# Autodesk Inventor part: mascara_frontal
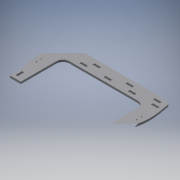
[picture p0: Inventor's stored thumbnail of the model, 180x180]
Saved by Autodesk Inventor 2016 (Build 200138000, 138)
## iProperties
Created: 2017-06
Part Number: mascara_frontal
Material: Generic
Document SubType Name: Modeling
Designer: laboratorioesan
Density: 1 g/cm^3
Appearance: Default
Author: laboratorioesan
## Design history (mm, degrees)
sketch "Sketch1"
  geometry: L1 (280, 0)-(340, 0) reference; L2 (340, 0)-(340, 18.5) reference; L3 (280, 18.5)-(340, 18.5) reference; L4 (280, 0)-(280, 18.5) reference; L5 (70, 0)-(130, 0) reference; L6 (130, 0)-(130, 18.5) reference; L7 (70, 18.5)-(130, 18.5) reference; L8 (70, 0)-(70, 18.5) reference; L9 (500, 0)-(560, 0) reference; L10 (560, 0)-(560, 18.5) reference; L11 (500, 18.5)-(560, 18.5) reference; L12 (500, 0)-(500, 18.5) reference; L13 (720, 0)-(780, 0) reference; L14 (780, 0)-(780, 18.5) reference; L15 (720, 18.5)-(780, 18.5) reference; L16 (720, 0)-(720, 18.5) reference; L17 (930, 0)-(990, 0) reference; L18 (990, 0)-(990, 18.5) reference; L19 (930, 18.5)-(990, 18.5) reference; L20 (930, 0)-(930, 18.5) reference; L21 (0, 0)-(0, 18.5) reference; L22 (130, -432.5)-(130, 0) reference; L23 (111.5, -432.5)-(111.5, 0) reference; L24 (930, -432.5)-(930, 0) reference; L25 (948.5, -432.5)-(948.5, 0) reference; L26 (1060, 0)-(1060, 18.5) reference; L27 (990, 104.496)-(70, 104.496); L28 (70, 104.496)-(0, 0); L29 (0, 0)-(0, -84.685); L30 (57, -270.723)-(130, -270.723); L31 (1060, 0)-(990, 104.496); L32 (130, -270.723)-(160, -270.723); L33 (160, -270.723)-(160, -30); L34 (160, -30)-(900, -30); L35 (900, -30)-(900, -270.723); L36 (900, -270.723)-(1003, -270.723); L37 (1003, -270.723)-(1060, -84.685); L38 (1060, -84.685)-(1060, 0); L39 (0, -84.685)-(57, -270.723)
  constraints: 26 end point, 4 perpendicular, 3 point on line, 2 horizontal, 2 horizontal alignment, 2 vertical, 2 vertical alignment
  dimensions: "d0" = 30 distance of L30.end L32.end; "d1" = 30 distance between parallel lines of L24 L35; "d2" = 30 horizontal distance of L17.start L34.end; "d3" = 70 distance between parallel lines of L29 L8; "d4" = 70 distance between parallel lines of L38 L18 (derived); "d6" = 103 distance of L35.end L36.end; "d7" = 103 distance of L30.start L32.end
extrude "Extrusion1" new body sketch "Sketch1" distance "d8" = 18.5; taper "d9" = 0 deg
fillet "Fillet1" dims "d10" = 60
fillet "Fillet2" dims "d11" = 60
sketch "Sketch2"
  geometry: L1 (930, 0)-(930, 18.5) reference; L2 (930, 18.5)-(990, 18.5) reference; L3 (990, 18.5)-(990, 0) reference; L4 (990, 0)-(930, 0) reference; L5 (720, 0)-(720, 18.5) reference; L6 (720, 18.5)-(780, 18.5) reference; L7 (780, 18.5)-(780, 0) reference; L8 (780, 0)-(720, 0) reference; L9 (500, 0)-(500, 18.5) reference; L10 (500, 18.5)-(560, 18.5) reference; L11 (560, 18.5)-(560, 0) reference; L12 (560, 0)-(500, 0) reference; L13 (70, 0)-(70, 18.5) reference; L14 (70, 18.5)-(130, 18.5) reference; L15 (130, 18.5)-(130, 0) reference; L16 (130, 0)-(70, 0) reference; L17 (280, 0)-(280, 18.5) reference; L18 (280, 18.5)-(340, 18.5) reference; L19 (340, 18.5)-(340, 0) reference; L20 (340, 0)-(280, 0) reference; L21 (52.176, 77.889)-(0, 0) reference; L22 (0, 0)-(0, -84.685) reference; L23 (0, -84.685)-(44.002, -228.3) reference; L24 (101.37, -270.723)-(160, -270.723) reference; L25 (160, -270.723)-(160, -90) reference; L26 (220, -30)-(840, -30) reference; L27 (900, -90)-(900, -270.723) reference; L28 (900, -270.723)-(958.63, -270.723) reference; L29 (1015.998, -228.3)-(1060, -84.685) reference; L30 (1060, -84.685)-(1060, 0) reference; L31 (1060, 0)-(1007.824, 77.889) reference; L32 (957.975, 104.496)-(102.025, 104.496) reference; L33 (960, 67)-(900, 67); L34 (900, 67)-(900, 48.5); L35 (900, 48.5)-(960, 48.5); L36 (960, 48.5)-(960, 67); L37 (710, 48.5)-(650, 48.5); L38 (650, 48.5)-(650, 67); L39 (650, 67)-(710, 67); L40 (710, 67)-(710, 48.5); L41 (410, 48.5)-(350, 48.5); L42 (350, 48.5)-(350, 67); L43 (350, 67)-(410, 67); L44 (410, 67)-(410, 48.5); L45 (160, 48.5)-(100, 48.5); L46 (100, 48.5)-(100, 67); L47 (100, 67)-(160, 67); L48 (160, 67)-(160, 48.5); L49 (948.5, -432.5)-(948.5, 0) reference; L50 (997, -100)-(978.5, -100); L51 (978.5, -100)-(978.5, -40); L52 (978.5, -40)-(997, -40); L53 (997, -40)-(997, -100); L54 (997, -155)-(978.5, -155); L55 (978.5, -155)-(978.5, -215); L56 (978.5, -215)-(997, -215); L57 (997, -215)-(997, -155); L58 (111.5, -432.5)-(111.5, 0) reference; L59 (81.5, -100)-(63, -100); L60 (63, -100)-(63, -40); L61 (63, -40)-(81.5, -40); L62 (81.5, -40)-(81.5, -100); L63 (81.5, -155)-(63, -155); L64 (63, -155)-(63, -215)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; A1 r 60 centre (102.025, 44.496) between (102.025, 104.496) and (52.176, 77.889) reference; A2 r 60 centre (101.37, -210.723) between (44.002, -228.3) and (101.37, -270.723) reference; A3 r 60 centre (220, -90) between (220, -30) and (160, -90) reference; A4 r 60 centre (840, -90) between (900, -90) and (840, -30) reference; A5 r 60 centre (958.63, -210.723) between (958.63, -270.723) and (1015.998, -228.3) reference; A6 r 60 centre (957.975, 44.496) between (1007.824, 77.889) and (957.975, 104.496) reference; 6 further points
  constraints: 64 end point, 16 parallel, 8 horizontal, 8 perpendicular, 7 horizontal alignment, 5 midpoint, 5 point on line, 4 vertical alignment
  dimensions: "d12" = 60 distance of L35.end L34.end; "d13" = 18.5 distance of L34.end L33.end; "d14" = 60 distance of L38.end L39.end; "d15" = 60 distance of L42.end L43.end; "d16" = 60 distance of L46.end L47.end; "d17" = 30 distance from line of L1.end L35; "d18" = 190 distance of L47.end L42.end; "d19" = 190 distance of L37.start L34.end; "d20" = 18.5 distance of L51.end L52.end; "d21" = 60 distance of L50.end L51.end; "d22" = 40 vertical distance of L3.end L52.end; "d23" = 60 distance of L55.end L54.end; "d24" = 30 distance between parallel lines of L49 L51; "d25" = 18.5 distance of L60.end L61.end; "d26" = 60 distance of L64.end L63.end; "d27" = 55 distance of L50.end L54.end; "d28" = 30 distance from line of L58 L59.start
extrude "Extrusion2" cut sketch "Sketch2" distance "d29" = 18.5; taper "d30" = 0 deg
sketch "Sketch3"
  geometry: L1 (81.5, -40)-(81.5, -100) reference; L2 (81.5, -100)-(63, -100) reference; L3 (63, -100)-(63, -40) reference; L4 (63, -40)-(81.5, -40) reference; L5 (997, -40)-(997, -100) reference; L6 (997, -100)-(978.5, -100) reference; L7 (978.5, -100)-(978.5, -40) reference; L8 (978.5, -40)-(997, -40) reference; L9 (410, 67)-(410, 48.5) reference; L10 (410, 48.5)-(350, 48.5) reference; L11 (350, 48.5)-(350, 67) reference; L12 (350, 67)-(410, 67) reference; L13 (900, 48.5)-(900, 67) reference; L14 (900, 67)-(960, 67) reference; L15 (960, 67)-(960, 48.5) reference; L16 (960, 48.5)-(900, 48.5) reference; L17 (710, 67)-(710, 48.5) reference; L18 (710, 48.5)-(650, 48.5) reference; L19 (650, 48.5)-(650, 67) reference; L20 (650, 67)-(710, 67) reference; L21 (160, 67)-(160, 48.5) reference; L22 (160, 48.5)-(100, 48.5) reference; L23 (100, 48.5)-(100, 67) reference; L24 (100, 67)-(160, 67) reference; L25 (978.5, -215)-(978.5, -155) reference; L26 (978.5, -155)-(997, -155) reference; L27 (997, -155)-(997, -215) reference; L28 (997, -215)-(978.5, -215) reference; L29 (63, -215)-(63, -155) reference; L30 (63, -155)-(81.5, -155) reference; L31 (81.5, -155)-(81.5, -215) reference; L32 (81.5, -215)-(63, -215) reference; L33 (930, 0)-(930, 18.5) reference; L34 (930, 18.5)-(990, 18.5) reference; L35 (990, 18.5)-(990, 0) reference; L36 (990, 0)-(930, 0) reference; L37 (720, 0)-(720, 18.5) reference; L38 (720, 18.5)-(780, 18.5) reference; L39 (780, 18.5)-(780, 0) reference; L40 (780, 0)-(720, 0) reference; L41 (500, 0)-(500, 18.5) reference; L42 (500, 18.5)-(560, 18.5) reference; L43 (560, 18.5)-(560, 0) reference; L44 (560, 0)-(500, 0) reference; L45 (70, 0)-(70, 18.5) reference; L46 (70, 18.5)-(130, 18.5) reference; L47 (130, 18.5)-(130, 0) reference; L48 (130, 0)-(70, 0) reference; L49 (280, 0)-(280, 18.5) reference; L50 (280, 18.5)-(340, 18.5) reference; L51 (340, 18.5)-(340, 0) reference; L52 (340, 0)-(280, 0) reference; L53 (52.176, 77.889)-(0, 0) reference; L54 (0, 0)-(0, -84.685) reference; L55 (0, -84.685)-(44.002, -228.3) reference; L56 (101.37, -270.723)-(160, -270.723) reference; L57 (160, -270.723)-(160, -90) reference; L58 (220, -30)-(840, -30) reference; L59 (900, -90)-(900, -270.723) reference; L60 (900, -270.723)-(958.63, -270.723) reference; L61 (1015.998, -228.3)-(1060, -84.685) reference; L62 (1060, -84.685)-(1060, 0) reference; L63 (1060, 0)-(1007.824, 77.889) reference; L64 (957.975, 104.496)-(102.025, 104.496) reference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; A1 r 60 centre (102.025, 44.496) between (102.025, 104.496) and (52.176, 77.889) reference; A2 r 60 centre (101.37, -210.723) between (44.002, -228.3) and (101.37, -270.723) reference; A3 r 60 centre (220, -90) between (220, -30) and (160, -90) reference; A4 r 60 centre (840, -90) between (900, -90) and (840, -30) reference; A5 r 60 centre (958.63, -210.723) between (958.63, -270.723) and (1015.998, -228.3) reference; A6 r 60 centre (957.975, 44.496) between (1007.824, 77.889) and (957.975, 104.496) reference; 1 further point
  constraints: 16 end point, 4 parallel, 2 horizontal, 2 perpendicular
extrude "Extrusion3" join sketch "Sketch3" distance "d31" = 18.5; taper "d32" = 0 deg
sketch "Sketch4"
  geometry: L1 (410, 67)-(410, 48.5) reference; L2 (410, 48.5)-(350, 48.5) reference; L3 (350, 48.5)-(350, 67) reference; L4 (350, 67)-(410, 67) reference; L5 (900, 48.5)-(900, 67) reference; L6 (900, 67)-(960, 67) reference; L7 (960, 67)-(960, 48.5) reference; L8 (960, 48.5)-(900, 48.5) reference; L9 (710, 67)-(710, 48.5) reference; L10 (710, 48.5)-(650, 48.5) reference; L11 (650, 48.5)-(650, 67) reference; L12 (650, 67)-(710, 67) reference; L13 (160, 67)-(160, 48.5) reference; L14 (160, 48.5)-(100, 48.5) reference; L15 (100, 48.5)-(100, 67) reference; L16 (100, 67)-(160, 67) reference; L17 (978.5, -215)-(978.5, -155) reference; L18 (978.5, -155)-(997, -155) reference; L19 (997, -155)-(997, -215) reference; L20 (997, -215)-(978.5, -215) reference; L21 (63, -215)-(63, -155) reference; L22 (63, -155)-(81.5, -155) reference; L23 (81.5, -155)-(81.5, -215) reference; L24 (81.5, -215)-(63, -215) reference; L25 (930, 0)-(930, 18.5) reference; L26 (930, 18.5)-(990, 18.5) reference; L27 (990, 18.5)-(990, 0) reference; L28 (990, 0)-(930, 0) reference; L29 (720, 0)-(720, 18.5) reference; L30 (720, 18.5)-(780, 18.5) reference; L31 (780, 18.5)-(780, 0) reference; L32 (780, 0)-(720, 0) reference; L33 (500, 0)-(500, 18.5) reference; L34 (500, 18.5)-(560, 18.5) reference; L35 (560, 18.5)-(560, 0) reference; L36 (560, 0)-(500, 0) reference; L37 (70, 0)-(70, 18.5) reference; L38 (70, 18.5)-(130, 18.5) reference; L39 (130, 18.5)-(130, 0) reference; L40 (130, 0)-(70, 0) reference; L41 (280, 0)-(280, 18.5) reference; L42 (280, 18.5)-(340, 18.5) reference; L43 (340, 18.5)-(340, 0) reference; L44 (340, 0)-(280, 0) reference; L45 (52.176, 77.889)-(0, 0) reference; L46 (0, 0)-(0, -84.685) reference; L47 (0, -84.685)-(44.002, -228.3) reference; L48 (101.37, -270.723)-(160, -270.723) reference; L49 (160, -270.723)-(160, -90) reference; L50 (220, -30)-(840, -30) reference; L51 (900, -90)-(900, -270.723) reference; L52 (900, -270.723)-(958.63, -270.723) reference; L53 (1015.998, -228.3)-(1060, -84.685) reference; L54 (1060, -84.685)-(1060, 0) reference; L55 (1060, 0)-(1007.824, 77.889) reference; L56 (957.975, 104.496)-(102.025, 104.496) reference; L57 (530, -30)-(530, -112.619); L58 (130, -1020.137)-(130, -1080.137) reference; L59 (130, -1080.137)-(111.5, -1080.137) reference; L60 (111.5, -1080.137)-(111.5, -1020.137) reference; L61 (111.5, -1020.137)-(130, -1020.137) reference; L62 (111.5, -787.5)-(111.5, -769) reference; L63 (111.5, -769)-(150, -769) reference; L64 (150, -769)-(150, -412.5) reference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; C1 r 5.25 at (50, -140); C2 r 5.25 at (1010, -140); A1 r 60 centre (102.025, 44.496) between (102.025, 104.496) and (52.176, 77.889) reference; A2 r 60 centre (101.37, -210.723) between (44.002, -228.3) and (101.37, -270.723) reference; A3 r 60 centre (220, -90) between (220, -30) and (160, -90) reference; A4 r 60 centre (840, -90) between (900, -90) and (840, -30) reference; A5 r 60 centre (958.63, -210.723) between (958.63, -270.723) and (1015.998, -228.3) reference; A6 r 60 centre (957.975, 44.496) between (1007.824, 77.889) and (957.975, 104.496) reference; A7 r 3569.02 centre (-3531.655, -709.325) between (0, -1224.41) and (25, -412.5) reference; A8 r 60 centre (102.025, 44.496) between (102.025, 104.496) and (52.176, 77.889) reference; 1 further point
  constraints: 18 end point, 3 point on line, 2 centre point, 2 parallel, 2 vertical, 1 horizontal, 1 midpoint, 1 perpendicular, 1 symmetric about line, 1 other
  dimensions: "d33" = 10.5 diameter of C1; "d34" = 140 vertical distance of L37.start C1.centre; "d35" = 20 horizontal distance of L37.start C1.centre; "d38" = 18.5 distance of L99.end L98.end; "d39" = 60 distance of L98.end L97.end; "d40" = 15 distance between parallel lines of L77 L100
extrude "Extrusion4" cut sketch "Sketch4" distance "d36" = 18.5; taper "d37" = 0 deg
sketch "Sketch6"
  geometry: L1 (410, 67)-(410, 48.5) reference; L2 (410, 48.5)-(350, 48.5) reference; L3 (350, 48.5)-(350, 67) reference; L4 (350, 67)-(410, 67) reference; L5 (900, 48.5)-(900, 67) reference; L6 (900, 67)-(960, 67) reference; L7 (960, 67)-(960, 48.5) reference; L8 (960, 48.5)-(900, 48.5) reference; L9 (710, 67)-(710, 48.5) reference; L10 (710, 48.5)-(650, 48.5) reference; L11 (650, 48.5)-(650, 67) reference; L12 (650, 67)-(710, 67) reference; L13 (160, 67)-(160, 48.5) reference; L14 (160, 48.5)-(100, 48.5) reference; L15 (100, 48.5)-(100, 67) reference; L16 (100, 67)-(160, 67) reference; L17 (978.5, -215)-(978.5, -155) reference; L18 (978.5, -155)-(997, -155) reference; L19 (997, -155)-(997, -215) reference; L20 (997, -215)-(978.5, -215) reference; L21 (63, -215)-(63, -155) reference; L22 (63, -155)-(81.5, -155) reference; L23 (81.5, -155)-(81.5, -215) reference; L24 (81.5, -215)-(63, -215) reference; L25 (930, 0)-(930, 18.5) reference; L26 (930, 18.5)-(990, 18.5) reference; L27 (990, 18.5)-(990, 0) reference; L28 (990, 0)-(930, 0) reference; L29 (720, 0)-(720, 18.5) reference; L30 (720, 18.5)-(780, 18.5) reference; L31 (780, 18.5)-(780, 0) reference; L32 (780, 0)-(720, 0) reference; L33 (500, 0)-(500, 18.5) reference; L34 (500, 18.5)-(560, 18.5) reference; L35 (560, 18.5)-(560, 0) reference; L36 (560, 0)-(500, 0) reference; L37 (70, 0)-(70, 18.5) reference; L38 (70, 18.5)-(130, 18.5) reference; L39 (130, 18.5)-(130, 0) reference; L40 (130, 0)-(70, 0) reference; L41 (280, 0)-(280, 18.5) reference; L42 (280, 18.5)-(340, 18.5) reference; L43 (340, 18.5)-(340, 0) reference; L44 (340, 0)-(280, 0) reference; L45 (52.176, 77.889)-(0, 0) reference; L46 (0, 0)-(0, -84.685) reference; L47 (0, -84.685)-(44.002, -228.3) reference; L48 (101.37, -270.723)-(160, -270.723) reference; L49 (160, -270.723)-(160, -90) reference; L50 (220, -30)-(840, -30) reference; L51 (900, -90)-(900, -270.723) reference; L52 (900, -270.723)-(958.63, -270.723) reference; L53 (1015.998, -228.3)-(1060, -84.685) reference; L54 (1060, -84.685)-(1060, 0) reference; L55 (1060, 0)-(1007.824, 77.889) reference; L56 (957.975, 104.496)-(102.025, 104.496) reference; L57 (948.5, -432.5)-(948.5, 0) reference; L58 (111.5, -432.5)-(111.5, 0) reference; L59 (1007.824, 77.889)-(1044.661, -134.75); L60 (150, -412.5)-(25, -412.5) reference; L61 (910, -412.5)-(1035, -412.5) reference; L62 (1044.661, -134.75)-(997, -290.306); L63 (1015.998, -228.3)-(1060, -84.685) reference; L64 (997, -290.306)-(997, -412.5)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; C1 r 5.25 at (50, -140) reference; C2 r 5.25 at (1010, -140) reference; C3 r 5.25 at (50, -140); A1 r 60 centre (102.025, 44.496) between (102.025, 104.496) and (52.176, 77.889) reference; A2 r 60 centre (101.37, -210.723) between (44.002, -228.3) and (101.37, -270.723) reference; A3 r 60 centre (220, -90) between (220, -30) and (160, -90) reference; A4 r 60 centre (840, -90) between (900, -90) and (840, -30) reference; A5 r 60 centre (958.63, -210.723) between (958.63, -270.723) and (1015.998, -228.3) reference; A6 r 60 centre (957.975, 44.496) between (1007.824, 77.889) and (957.975, 104.496) reference; A7 r 60 centre (957.975, 44.496) between (1007.824, 77.889) and (957.975, 104.496) reference; A8 r 60 centre (101.37, -210.723) between (44.002, -228.3) and (101.37, -270.723); A9 r 60 centre (102.025, 44.496) between (102.025, 104.496) and (52.176, 77.889); A10 r 60 centre (102.025, 44.496) between (102.025, 104.496) and (52.176, 77.889); 1 further point
  constraints: 34 end point, 8 symmetric about line, 6 point on circle, 5 point on line, 4 centre point, 1 collinear, 1 midpoint, 1 perpendicular, 1 vertical, 4 other
extrude "Extrusion5" cut sketch "Sketch6" distance "d41" = 18.5; taper "d42" = 0 deg
sketch "Sketch7"
  geometry: L1 (280, 0)-(280, 18.5) reference; L2 (280, 18.5)-(340, 18.5) reference; L3 (340, 18.5)-(340, 0) reference; L4 (340, 0)-(280, 0) reference; L5 (70, 0)-(70, 18.5) reference; L6 (70, 18.5)-(130, 18.5) reference; L7 (130, 18.5)-(130, 0) reference; L8 (130, 0)-(70, 0) reference; L9 (500, 0)-(500, 18.5) reference; L10 (500, 18.5)-(560, 18.5) reference; L11 (560, 18.5)-(560, 0) reference; L12 (560, 0)-(500, 0) reference; L13 (720, 0)-(720, 18.5) reference; L14 (720, 18.5)-(780, 18.5) reference; L15 (780, 18.5)-(780, 0) reference; L16 (780, 0)-(720, 0) reference; L17 (930, 0)-(930, 18.5) reference; L18 (930, 18.5)-(990, 18.5) reference; L19 (990, 18.5)-(990, 0) reference; L20 (990, 0)-(930, 0) reference; L21 (63, -215)-(63, -155) reference; L22 (63, -155)-(81.5, -155) reference; L23 (81.5, -155)-(81.5, -215) reference; L24 (81.5, -215)-(63, -215) reference; L25 (978.5, -215)-(978.5, -155) reference; L26 (978.5, -155)-(997, -155) reference; L27 (997, -155)-(997, -215) reference; L28 (997, -215)-(978.5, -215) reference; L29 (160, 67)-(160, 48.5) reference; L30 (160, 48.5)-(100, 48.5) reference; L31 (100, 48.5)-(100, 67) reference; L32 (100, 67)-(160, 67) reference; L33 (710, 67)-(710, 48.5) reference; L34 (710, 48.5)-(650, 48.5) reference; L35 (650, 48.5)-(650, 67) reference; L36 (650, 67)-(710, 67) reference; L37 (900, 48.5)-(900, 67) reference; L38 (900, 67)-(960, 67) reference; L39 (960, 67)-(960, 48.5) reference; L40 (960, 48.5)-(900, 48.5) reference; L41 (410, 67)-(410, 48.5) reference; L42 (410, 48.5)-(350, 48.5) reference; L43 (350, 48.5)-(350, 67) reference; L44 (350, 67)-(410, 67) reference; L45 (1044.661, -134.75)-(1007.824, 77.889) reference; L46 (957.975, 104.496)-(102.025, 104.496) reference; L47 (52.176, 77.889)-(15.339, -134.75) reference; L48 (15.339, -134.75)-(44.002, -228.3) reference; L49 (101.37, -270.723)-(160, -270.723) reference; L50 (160, -270.723)-(160, -90) reference; L51 (220, -30)-(840, -30) reference; L52 (900, -90)-(900, -270.723) reference; L53 (900, -270.723)-(958.63, -270.723) reference; L54 (1015.998, -228.3)-(1044.661, -134.75) reference; L55 (910, -412.5)-(1035, -412.5) reference; L56 (150, -412.5)-(25, -412.5) reference; L57 (900, -90)-(900, -270.723) reference; L58 (900, -270.723)-(900, -412.5); L59 (1040.089, -108.361)-(1045.57, -140); L60 (1045.57, -140)-(997, -298.524); L61 (997, -298.524)-(997, -412.5); L62 (900, -412.5)-(997, -412.5); L63 (18.374, -117.231)-(14.43, -140); L64 (957.975, 104.496)-(102.025, 104.496) reference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; C1 r 5.25 at (1010, -140) reference; C2 r 5.25 at (50, -140) reference; C3 r 5.25 at (50, -140); C4 r 5.25 at (50, -140); A1 r 60 centre (957.975, 44.496) between (1007.824, 77.889) and (957.975, 104.496) reference; A2 r 60 centre (102.025, 44.496) between (102.025, 104.496) and (52.176, 77.889) reference; A3 r 60 centre (101.37, -210.723) between (44.002, -228.3) and (101.37, -270.723) reference; A4 r 60 centre (220, -90) between (220, -30) and (160, -90) reference; A5 r 60 centre (840, -90) between (900, -90) and (840, -30) reference; A6 r 60 centre (958.63, -210.723) between (958.63, -270.723) and (1015.998, -228.3) reference; A7 r 3569.02 centre (-3531.655, -709.325) between (0, -1224.41) and (25, -412.5) reference; A8 r 3569.02 centre (4591.655, -709.325) between (1035, -412.5) and (1060, -1224.41) reference; A9 r 60 centre (101.37, -210.723) between (44.002, -228.3) and (101.37, -270.723); 1 further point
  constraints: 58 end point, 10 symmetric about line, 5 point on line, 3 centre point, 3 parallel, 3 vertical, 2 point on circle, 1 collinear, 1 horizontal, 1 horizontal alignment, 1 midpoint, 1 perpendicular, 2 other
  dimensions: "d43" = 10.5 diameter of C3; "d44" = 60 distance of L80.end L81.end; "d45" = 30 distance between parallel lines of L55 L80; "d46" = 18.5 distance of L80.start L80.end; "d47" = 10 distance between parallel lines of L90 L81
extrude "Extrusion6" join sketch "Sketch7" distance "d48" = 18.5; taper "d49" = 0 deg
sketch "Sketch8"
  geometry: L1 (83, -322.5)-(101.5, -322.5) reference; L2 (101.5, -322.5)-(101.5, -382.5) reference; L3 (101.5, -382.5)-(83, -382.5) reference; L4 (83, -382.5)-(83, -322.5) reference; L5 (977, -322.5)-(977, -382.5) reference; L6 (977, -382.5)-(958.5, -382.5) reference; L7 (958.5, -382.5)-(958.5, -322.5) reference; L8 (958.5, -322.5)-(977, -322.5) reference; L9 (280, 0)-(280, 18.5) reference; L10 (280, 18.5)-(340, 18.5) reference; L11 (340, 18.5)-(340, 0) reference; L12 (340, 0)-(280, 0) reference; L13 (70, 0)-(70, 18.5) reference; L14 (70, 18.5)-(130, 18.5) reference; L15 (130, 18.5)-(130, 0) reference; L16 (130, 0)-(70, 0) reference; L17 (500, 0)-(500, 18.5) reference; L18 (500, 18.5)-(560, 18.5) reference; L19 (560, 18.5)-(560, 0) reference; L20 (560, 0)-(500, 0) reference; L21 (720, 0)-(720, 18.5) reference; L22 (720, 18.5)-(780, 18.5) reference; L23 (780, 18.5)-(780, 0) reference; L24 (780, 0)-(720, 0) reference; L25 (930, 0)-(930, 18.5) reference; L26 (930, 18.5)-(990, 18.5) reference; L27 (990, 18.5)-(990, 0) reference; L28 (990, 0)-(930, 0) reference; L29 (160, 67)-(160, 48.5) reference; L30 (160, 48.5)-(100, 48.5) reference; L31 (100, 48.5)-(100, 67) reference; L32 (100, 67)-(160, 67) reference; L33 (710, 67)-(710, 48.5) reference; L34 (710, 48.5)-(650, 48.5) reference; L35 (650, 48.5)-(650, 67) reference; L36 (650, 67)-(710, 67) reference; L37 (900, 48.5)-(900, 67) reference; L38 (900, 67)-(960, 67) reference; L39 (960, 67)-(960, 48.5) reference; L40 (960, 48.5)-(900, 48.5) reference; L41 (410, 67)-(410, 48.5) reference; L42 (410, 48.5)-(350, 48.5) reference; L43 (350, 48.5)-(350, 67) reference; L44 (350, 67)-(410, 67) reference; L45 (52.176, 77.889)-(14.43, -140) reference; L46 (14.43, -140)-(63, -298.524) reference; L47 (63, -298.524)-(63, -412.5) reference; L48 (63, -412.5)-(160, -412.5) reference; L49 (160, -412.5)-(160, -90) reference; L50 (220, -30)-(840, -30) reference; L51 (900, -90)-(900, -412.5) reference; L52 (900, -412.5)-(997, -412.5) reference; L53 (997, -412.5)-(997, -298.524) reference; L54 (997, -298.524)-(1045.57, -140) reference; L55 (1045.57, -140)-(1007.824, 77.889) reference; L56 (957.975, 104.496)-(102.025, 104.496) reference; C1 r 5.25 at (1010, -140) reference; C2 r 5.25 at (50, -140) reference; C3 r 5.25 at (986, -140); C4 r 5.25 at (74, -140); A1 r 60 centre (220, -90) between (220, -30) and (160, -90) reference; A2 r 60 centre (840, -90) between (900, -90) and (840, -30) reference; A3 r 60 centre (957.975, 44.496) between (1007.824, 77.889) and (957.975, 104.496) reference; A4 r 60 centre (102.025, 44.496) between (102.025, 104.496) and (52.176, 77.889) reference; 1 further point
  constraints: 2 centre point
  dimensions: "d50" = 10.5 diameter of C3; "d51" = 24 distance of C1.centre C3.centre; "d52" = 10.5 diameter of C4; "d53" = 24 distance of C2.centre C4.centre
extrude "Extrusion7" cut sketch "Sketch8" distance "d54" = 18.5; taper "d55" = 0 deg
sketch "Sketch9"
  geometry: L1 (111.5, -432.5)-(111.5, 0) reference; L2 (83, -322.5)-(101.5, -322.5) reference; L3 (101.5, -322.5)-(101.5, -382.5) reference; L4 (101.5, -382.5)-(83, -382.5) reference; L5 (83, -382.5)-(83, -322.5) reference; L6 (977, -322.5)-(977, -382.5) reference; L7 (977, -382.5)-(958.5, -382.5) reference; L8 (958.5, -382.5)-(958.5, -322.5) reference; L9 (958.5, -322.5)-(977, -322.5) reference; L10 (280, 0)-(280, 18.5) reference; L11 (280, 18.5)-(340, 18.5) reference; L12 (340, 18.5)-(340, 0) reference; L13 (340, 0)-(280, 0) reference; L14 (70, 0)-(70, 18.5) reference; L15 (70, 18.5)-(130, 18.5) reference; L16 (130, 18.5)-(130, 0) reference; L17 (130, 0)-(70, 0) reference; L18 (500, 0)-(500, 18.5) reference; L19 (500, 18.5)-(560, 18.5) reference; L20 (560, 18.5)-(560, 0) reference; L21 (560, 0)-(500, 0) reference; L22 (720, 0)-(720, 18.5) reference; L23 (720, 18.5)-(780, 18.5) reference; L24 (780, 18.5)-(780, 0) reference; L25 (780, 0)-(720, 0) reference; L26 (930, 0)-(930, 18.5) reference; L27 (930, 18.5)-(990, 18.5) reference; L28 (990, 18.5)-(990, 0) reference; L29 (990, 0)-(930, 0) reference; L30 (160, 67)-(160, 48.5) reference; L31 (160, 48.5)-(100, 48.5) reference; L32 (100, 48.5)-(100, 67) reference; L33 (100, 67)-(160, 67) reference; L34 (710, 67)-(710, 48.5) reference; L35 (710, 48.5)-(650, 48.5) reference; L36 (650, 48.5)-(650, 67) reference; L37 (650, 67)-(710, 67) reference; L38 (900, 48.5)-(900, 67) reference; L39 (900, 67)-(960, 67) reference; L40 (960, 67)-(960, 48.5) reference; L41 (960, 48.5)-(900, 48.5) reference; L42 (410, 67)-(410, 48.5) reference; L43 (410, 48.5)-(350, 48.5) reference; L44 (350, 48.5)-(350, 67) reference; L45 (350, 67)-(410, 67) reference; L46 (52.176, 77.889)-(14.43, -140) reference; L47 (14.43, -140)-(63, -298.524) reference; L48 (63, -298.524)-(63, -412.5) reference; L49 (63, -412.5)-(160, -412.5) reference; L50 (160, -412.5)-(160, -90) reference; L51 (220, -30)-(840, -30) reference; L52 (900, -90)-(900, -412.5) reference; L53 (900, -412.5)-(997, -412.5) reference; L54 (997, -412.5)-(997, -298.524) reference; L55 (997, -298.524)-(1045.57, -140) reference; L56 (1045.57, -140)-(1007.824, 77.889) reference; L57 (957.975, 104.496)-(102.025, 104.496) reference; C1 r 5.25 at (986, -140) reference; C2 r 5.25 at (74, -140) reference; C3 r 5.25 at (1010, -140) reference; C4 r 5.25 at (50, -140) reference; A1 r 60 centre (220, -90) between (220, -30) and (160, -90) reference; A2 r 60 centre (840, -90) between (900, -90) and (840, -30) reference; A3 r 60 centre (957.975, 44.496) between (1007.824, 77.889) and (957.975, 104.496) reference; A4 r 60 centre (102.025, 44.496) between (102.025, 104.496) and (52.176, 77.889) reference; 1 further point
extrude "Extrusion8" join sketch "Sketch9" distance "d56" = 18.5; taper "d57" = 0 deg
fillet "Fillet3" dims "d58" = 500
sketch "Sketch10"
  geometry: L1 (1037.5, -132.5)-(1056, -132.5) reference; L2 (1056, -132.5)-(1056, -192.5) reference; L3 (1056, -192.5)-(1037.5, -192.5) reference; L4 (1037.5, -192.5)-(1037.5, -132.5) reference; L5 (1002.5, -125.661)-(1027.5, -125.661) reference; L6 (1027.5, -125.661)-(1027.5, -144.161) reference; L7 (1027.5, -144.161)-(1002.5, -144.161) reference; L8 (1002.5, -144.161)-(1002.5, -125.661) reference; L9 (1066, -205)-(1066, -120) reference; L10 (1066, -120)-(1011.617, -120) reference; L11 (1005.816, -165.76)-(1036, -205) reference; L12 (1036, -205)-(1066, -205) reference; L13 (1037.5, -162.5)-(1031.754, -162.5); L14 (957.975, 104.496)-(102.025, 104.496) reference; L15 (530, 104.496)-(530, 58.241); C1 r 5.25 at (986, -140) reference; C2 r 5.25 at (986, -185); C3 r 5.25 at (74, -185); A1 r 32.5 centre (986, -140) between (1011.617, -120) and (1005.816, -165.76) reference; 1 further point
  constraints: 4 end point, 2 centre point, 2 midpoint, 1 horizontal, 1 symmetric about line, 1 vertical, 1 other
  dimensions: "d59" = 10.5 diameter of C2; "d60" = 22.5 vertical distance of L13.start C2.centre
extrude "Extrusion9" cut sketch "Sketch10" distance "d61" = 18.5; taper "d62" = 0 deg
body "Solid1"
node "Reference1"
node "Reference2"
node "Reference3"
node "Reference4"
node "Reference5"
node "Reference6"
node "Reference7"
node "Reference8"
node "Reference9"
node "Reference10"
node "Reference11"
node "Projected Loop1"
node "Reference12"
node "Reference13"
node "Projected Loop2"
node "Projected Loop3"
node "Reference14"
node "Projected Loop4"
node "Reference15"
node "Reference16"
node "Reference17"
node "Reference18"
node "Projected Loop5"
node "Reference19"
node "Reference20"
node "Reference21"
node "Reference22"
node "Reference23"
node "Projected Loop6"
node "Reference24"
node "Projected Loop7"
node "Reference25"
